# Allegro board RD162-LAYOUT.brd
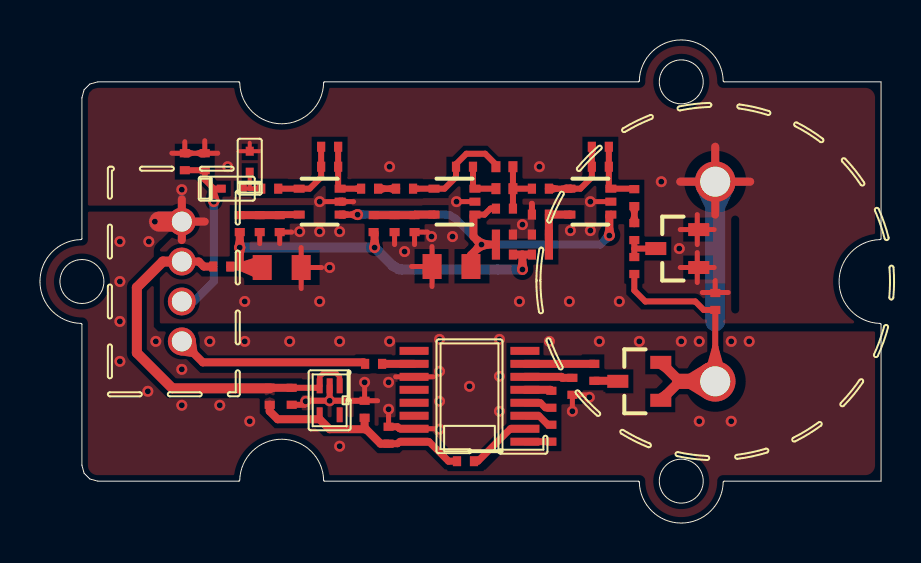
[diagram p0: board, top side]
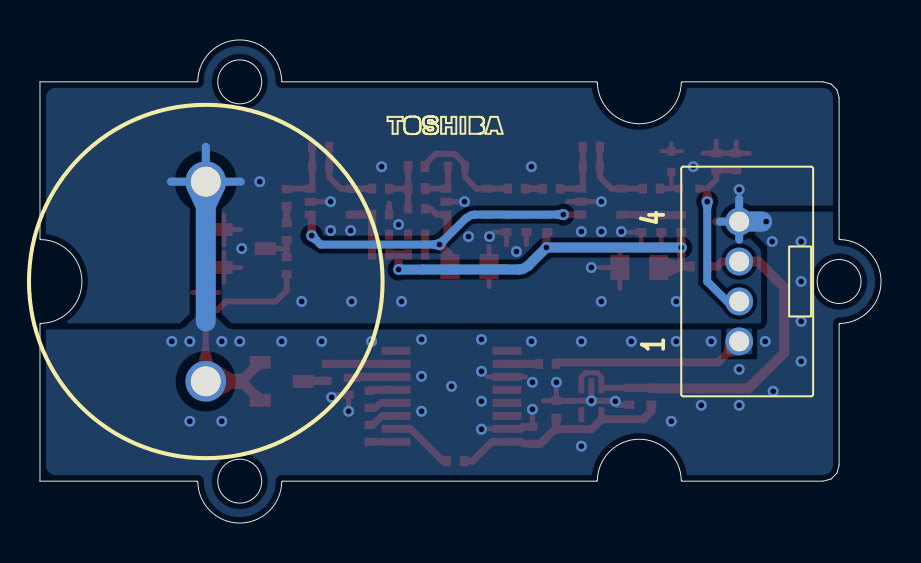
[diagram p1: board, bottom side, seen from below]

Outline 42.1 x 24.2 mm; copper layers: TOP, BOTTOM. Coordinates in mm from the lower left corner of the outline.
Outline path: circle c2.1,12.1 r1.1 ; circle c32.1,22.1 r1.1 ; circle c32.1,2.1 r1.1 ; 2.05,14.2 2.09,14.21 2.1,14.25 2.1,21.3 2.21,21.7 2.5,21.99 2.9,22.1 9.95,22.1 9.99,22.09 10,22.05 arc(12.1,20) 14.2,22.05 14.21,22.09 14.25,22.1 29.95,22.1 29.99,22.11 30,22.15 arc(32.1,24.2) 34.2,22.15 34.21,22.11 34.25,22.1 42.1,22.1 42.1,14.25 42.09,14.21 42.05,14.2 arc(40,12.1) 42.05,10 42.09,9.99 42.1,9.95 42.1,2.1 34.25,2.1 34.21,2.09 34.2,2.05 arc(32.1,0) 30,2.05 29.99,2.09 29.95,2.1 14.25,2.1 14.21,2.11 14.2,2.15 arc(12.1,4.2) 10,2.15 9.99,2.11 9.95,2.1 2.9,2.1 2.5,2.21 2.21,2.5 2.1,2.9 2.1,9.95 2.09,9.99 2.05,10 arc(0,12.1) 2.05,14.2

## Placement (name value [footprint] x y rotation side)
C1  -  [KC00050ACP]  25.6 4.5 270 top
C2  -  [KC00050ACP]  21.3 3.1 180 top
C3  -  [KC00050ACP]  17.45 4.4 270 top
C4  -  [KC00050ACP]  25.6 6.2 270 top
C5  -  [KC00050ACP]  26.65 6.85 90 top
C6  -  [KC00050ACS]  16.25 5.7 270 top
C7  -  [KC00050ACP]  27.75 7.55 90 top
C8  -  [KC00050ACP]  12.6 6.35 90 top
C9  -  [DC834K0ACP]  28.05 18.85 180 top
C10  -  [KC00050ACP]  29.75 14.6 90 top
C11  -  [DC834K0ACP]  14.5 18.85 180 top
C12  -  [KC01540AKP01]  23.25 17.85 180 top
C13  -  [KC00060ATP]  12.1 12.8 180 top
C14  -  [KC01540AKP01]  23.25 16.75 180 top
C15  -  [KC00050ACP]  18.25 16.75 180 top
C16  -  [KC00050ACP]  25.05 14.45 0 top
C17  -  [KC00050ACP]  25.05 15.45 0 top
C18  -  [KC00050ACP]  17.75 15 90 top
C19  -  [KC00050ACP]  18.75 15 90 top
C20  -  [KC00050ACP]  11.5 16.75 180 top
C21  -  [KC00060ATP]  20.6 12.85 0 top
C22  -  [DC834K0ACP]  8.25 18.1 270 top
C23  -  [KC00050ACP]  12 15 90 top
C24  -  [KC00050ACP]  11 15 90 top
CN1  -  [CUP10060ATP]  7.1 9.1 90 bottom
D1  -  [MMK01261AKP]  30 7.1 90 top
D2  -  [MMK01261AKP]  31.9 13.75 90 top
D3  -  [MM00820ACP]  9.6 16.75 180 top
D4  -  [MM00820ACP]  10.5 18.1 270 top
JP1  -  [KC00050ACP]  11.5 6.35 90 top
NOREF  -  []  25.55 18.65 0 top
R1  -  [DR824K0ACP]  16.7 7.97 180 top
R2  -  [KC00050ACP]  9.1 12.85 180 top
R3  -  [DR824K0ACP]  29.75 12.9 90 top
R4  -  [KC00050ACP]  29.75 16.3 90 top
R5  -  [KC00050ACP]  28.05 17.85 180 top
R6  -  [DR824K0ACP]  21.25 17.85 0 top
R7  -  [KC00050ACP]  25.05 16.75 180 top
R8  -  [DR824K0ACP]  16.5 16.75 180 top
R9  -  [DR824K0ACP]  14.5 17.85 180 top
R10  -  [KC00050ACP]  25.05 13.45 180 top
R11  -  [DR824K0ACP]  33.8 11.1 90 top
R12  -  [KC00050ACP]  16.7 15 270 top
R13  -  [DR824K0ACP]  23.25 15.75 180 top
R14  -  [DR824K0ACP]  23.25 14.45 0 top
R15  -  [DR824K0ACP]  23.25 13.45 0 top
R16  -  [KC00050ACP]  10 15 270 top
R17  -  [KC00050ACP]  7.25 18.1 90 top
U1  -  [DIA817C]  14.5 6.15 180 top
U2  -  [DIA863C]  21.5 6.35 90 top
U3  -  [MM00380ACP]  27.55 16.1 90 top
U4  -  [MM00380ACP]  20.75 16.1 90 top
U5  -  [RDP10030ATP]  33.8 7.1 90 bottom
U6  -  [MM00380ACP]  14 16.1 90 top

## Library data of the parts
C1-C5 C7 C8 C17 C19 C24 = GDM030002515: alternate symbols: (T:KC00050ACP;B:KC00050BCP)
C6 = GDM030000207: alternate symbols: (T:KC00050ACS;B:KC00050BCS)
C9 = G36030133319: alternate symbols: (T:DC834K0ACP;B:DC834K0BCP)
C10 C15 = GDM030002207: alternate symbols: (T:KC00050ACP;B:KC00050BCP)
C11 = G36030133067: alternate symbols: (T:DC834K0ACP;B:DC834K0BCP)
C12 C14 = GAS030000198: alternate symbols: (T:KC01540AKP01;B:KC01540BKP01)
C13 = GDM030001363: alternate symbols: (T:KC00060ATP;B:KC00060BTP)
C16 C18 C20 C23 = GDM030002441: alternate symbols: (T:KC00050ACP;B:KC00050BCP)
C21 = GDM030002136: alternate symbols: (T:KC00060ATP;B:KC00060BTP)
C22 = G36030133234: alternate symbols: (T:DC834K0ACP;B:DC834K0BCP)
CN1 = K22S001P: alternate symbols: (T:CUP10060ATP;B:CUP10060BTP)
D1 D2 = K4200526: alternate symbols: (T:MMK01261AKP;B:MMK01261BKP)
D3 D4 = GDM420000214: alternate symbols: (T:MM00820ACP;B:MM00820BCP)
JP1 R2 R10 R12 R16 = GDM010002886: alternate symbols: (T:KC00050ACP;B:KC00050BCP)
R1 R3 R14 R15 = GDM010001350: alternate symbols: (T:DR824K0ACP;B:DR824K0BCP)
R4 R17 = GDM010004244: alternate symbols: (T:KC00050ACP;B:KC00050BCP)
R5 = GDM010001678: alternate symbols: (T:KC00050ACP;B:KC00050BCP)
R6 = G36010118497: alternate symbols: (T:DR824K0ACP;B:DR824K0BCP)
R7 = K0100567: alternate symbols: (T:KC00050ACP;B:KC00050BCP)
R8 = G36010118343: alternate symbols: (T:DR824K0ACP;B:DR824K0BCP)
R9 = G36010118060: alternate symbols: (T:DR824K0ACP;B:DR824K0BCP)
R11 = G36010118633: alternate symbols: (T:DR824K0ACP;B:DR824K0BCP)
R13 = G36010118619: alternate symbols: (T:DR824K0ACP;B:DR824K0BCP)
U1 = GDM470001887: alternate symbols: (T:DIA817C;B:DIA917C)
U2 = K47S002D: alternate symbols: (T:DIA863C;B:DIA963C)
U3 U4 U6 = K47S002A: alternate symbols: (T:MM00380ACP;B:MM00380BCP)
U5 = K30S0001: alternate symbols: (T:RDP10030ATP;B:RDP10030BTP)

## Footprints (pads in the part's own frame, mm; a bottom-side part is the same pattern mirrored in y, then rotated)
CUP10060ATP
  round 1.397 hole 1: 1(0,0) 2(2,0) 3(4,0) 4(6,0)
DC834K0ACP
  rect 0.41x0.5 smd: 1(-0.425,0) 2(0.425,0)
DIA817C
  rect 0.3x0.75 smd: 1(-0.5,-0.725) 2(0,-0.725) 3(0.5,-0.725) 4(0.5,0.725) 5(-0.5,0.725)
DIA863C
  rect 0.4x1.45 smd: 1(-2.275,-2.775) 2(-1.625,-2.775) 3(-0.975,-2.775) 4(-0.325,-2.775) 5(0.325,-2.775) 6(0.975,-2.775) 7(1.625,-2.775) 8(2.275,-2.775) 9(2.275,2.775) 10(1.625,2.775) 11(0.975,2.775) 12(0.325,2.775) 13(-0.325,2.775) 14(-0.975,2.775) 15(-1.625,2.775) 16(-2.275,2.775)
DR824K0ACP
  rect 0.41x0.5 smd: 1(-0.425,0) 2(0.425,0)
KC00050ACP
  rect 0.41x0.5 smd: 1(-0.425,0) 2(0.425,0)
KC00050ACS
  rect 0.41x0.5 smd: 1(-0.425,0) 2(0.425,0)
KC00060ATP
  rect 0.95x1.25 smd: 1(-0.975,0) 2(0.975,0)
KC01540AKP01
  rect 0.45x0.55 smd: 1(-0.425,0) 2(0.425,0)
MM00380ACP
  rect 0.4x0.55 smd: 1(-0.65,-1.025) 2(0,-1.025) 3(0.65,-1.025) 4(0.65,1.025) 5(-0.65,1.025)
MM00820ACP
  rect 0.45x0.4 smd: A(-0.525,0) C(0.525,0)
MMK01261AKP
  rect 0.65x1.05 smd: A(-0.95,-1.075) AC(0,1.075) C(0.95,-1.075)
RDP10030ATP
  round 2.032 hole 1.5: 1(0,0) 2(10,0)

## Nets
GND: C3.1(TP-1) C5.1(TP-1) C6.1(TP-1) C8.1(TP-1) C13.1(TP-1) C16.1(TP-1) C17.1(TP-1) C18.1(TP-1) C19.1(TP-1) C21.1(TP-1) C22.1(TP-1) C23.1(TP-1) C24.1(TP-1) CN1.4 D2.A D2.C D4.A R11.2(TP-1) R14.2(TP-1) R17.2(TP-1) U1.2 U2.11 U2.15 U3.2 U4.2 U5.2(TP-1) U6.2
VCC: C13.2(TP-1) R2.1(TP-1) R10.2(TP-1) R12.2(TP-1) R15.2(TP-1) R16.2(TP-1)
SIG76: D1.A D1.C R3.1(TP-1) R11.1(TP-1) U5.1(TP-1)
SIG78: C10.2(TP-1) R4.1(TP-1)
SIG83: C16.2(TP-1) C17.2(TP-1) R10.1(TP-1) U3.5
SIG86: C12.1(TP-1) C14.1(TP-1) R7.2(TP-1) R13.1(TP-1)
SIG109: C1.2(TP-1) U2.1
SIG110: C1.1(TP-1) U2.3
SIG111: C4.2(TP-1) U2.4
SIG112: C4.1(TP-1) U2.5
SIG113: C2.1(TP-1) U2.2
SIG127: C7.2(TP-1) U2.7
SIG130: R1.1(TP-1) U2.10
SIG131: CN1.1 R1.2(TP-1)
SIG132: C7.1(TP-1) D1.AC
SIG136: C9.1(TP-1) R4.2(TP-1) R5.1(TP-1) U3.3
SIG137: C9.2(TP-1) R5.2(TP-1) R7.1(TP-1) U3.4
SIG138: C18.2(TP-1) C19.2(TP-1) R12.1(TP-1) U4.5
SIG141: C12.2(TP-1) C15.1(TP-1) R6.1(TP-1) U4.4
SIG143: C11.1(TP-1) R8.2(TP-1) R9.1(TP-1) U6.3
SIG145: C23.2(TP-1) C24.2(TP-1) R16.1(TP-1) U6.5
SIG146: C11.2(TP-1) C20.1(TP-1) R9.2(TP-1) U6.4
SIG147: C20.2(TP-1) D3.A D4.C
SIG152: C2.2(TP-1) C3.2(TP-1) C6.2(TP-1) JP1.1(TP-1) U1.4 U2.16
SIG154: C8.2(TP-1) CN1.3 JP1.2(TP-1) R2.2(TP-1) U1.1 U1.3
SIG155: C22.2(TP-1) CN1.2 D3.C R17.1(TP-1)
SIG156: C10.1(TP-1) D2.AC R3.2(TP-1)
SIG157: C14.2(TP-1) R6.2(TP-1) U4.3
SIG159: C15.2(TP-1) R8.1(TP-1)
SIG162: C5.2(TP-1) U2.6
VCC/2: C21.2(TP-1) R13.2(TP-1) R14.1(TP-1) R15.1(TP-1) U3.1 U4.1 U6.1

Pads without a net: U1 5; U2 8 9 12 13 14

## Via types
v1: diameter 0.55, hole 0.3, TOP to BOTTOM, 73 vias

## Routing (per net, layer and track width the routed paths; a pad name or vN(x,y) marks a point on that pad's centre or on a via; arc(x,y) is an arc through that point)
GND: length 66.9
  TOP w0.2: D4.A 11,18.62 ; D4.A 9.95,18.62 ; D4.A 10.5,19.05
  TOP w0.25: 12.6,14.57 C23.1 12,14 ; 16.9,6.12 C6.1 v1(16.25,7.05) ; 32.9,13.55 32.9,12.05 ; C13.1 14.1,12.8 ; C13.1 13.07,11.75 ; C13.1 13.07,13.8 ; 21.74,16.1 20.95,16.1 ; 17.8,7.32 U2.11 19.7,7.32 ; 26.65,5.8 C5.1 27.3,6.42 ; 33.75,14.7 D2.C 32.9,14.7 ; C21.1 19.62,13.85 ; C21.1 19.62,11.85 ; C21.1 18.6,12.85 ; 33.15,11.55 34.45,11.55 ; 32.05,12.8 D2.A 33.75,12.8 ; 18.75,13.95 C19.1 19.4,14.57 ; 33.8,12.15 R11.2 ; 15.12,16.1 15.7,16.1 ; 32.9,14.7 32.05,14.7 ; 32.9,14.7 32.9,13.95 ; 32.9,14.7 32.9,15.45 ; 6.6,18.52 7.25,18.52 7.25,19.1 ; 14.99,16.1 v1(14,16.1) ; v1(17.45,5.7) C3.1 ; C24.1 11,14 ; 7.39,18.52 8.11,18.52 ; 8.9,18.52 8.25,18.52 8.25,19.15 ; C18.1 17.75,13.95 ; 28.54,16.1 27.75,16.1 ; U2.15 19.75,4.72
  TOP w0.3: v1(14.5,6.12) 13.45,6.12 13.25,5.92 C8.1 ; v1(14.5,6.12) C6.1 ; v1(14.5,6.12) U1.2 ; C17.1 24.62,16
  TOP w0.35: C3.1 17.9,4.82 18,4.72 U2.15
  TOP w0.4: CN1.4 8.25,15.1 ; CN1.4 7.1,16.2 ; CN1.4 7.1,14.17 ; U5.2 33.8,15.45 ; U5.2 33.8,18.85 ; U5.2 35.55,17.1 ; U5.2 32.05,17.1 ; U6.2 15.12,16.1
  TOP w0.41: 8.11,18.52 8.25,18.52 ; 7.25,18.52 7.39,18.52
  TOP w1: CN1.4 5.97,15.1
  BOTTOM w0.4: CN1.4 8.06,15.1 ; CN1.4 7.1,16.25 ; CN1.4 7.1,14.2 ; U5.2 32.05,17.1 ; U5.2 35.55,17.1 ; U5.2 33.8,18.85
  BOTTOM w1: CN1.4 5.95,15.1 ; U5.2 33.8,10.1
  vias: v1(4,14.1) v1(4,12.1) v1(4,10.1) v1(4,8.1) v1(5.4,6.6) v1(5.45,14.1) v1(5.75,15.1) v1(5.8,9.1) v1(7.1,16.7) v1(7.1,7.7) v1(7.1,5.9) v1(8.5,9.1) v1(9,5.9) v1(9.4,17.85) v1(10.25,11.1) v1(10.25,9.1) v1(10.5,5.1) v1(12.5,9.1) v1(13,14.6) v1(13.3,6.1) v1(14,14.6) v1(14,11.1) v1(14.5,12.8) v1(15,14.6) v1(15,9.1) v1(15,3.85) v1(17.45,7.05) v1(17.5,17.85) v1(17.5,9.1) v1(18.25,13.6) v1(19.6,14.35) v1(20,9.2) v1(20,7.6) v1(20,6.1) v1(20,4.7) v1(20.65,14.35) v1(20.85,16.1) v1(21.5,6.85) v1(23,9.2) v1(23,7.35) v1(23,5.6) v1(24,11.1) v1(24.15,14.95) v1(25,17.85) v1(25.5,9.1) v1(26.5,11.1) v1(26.55,14.65) v1(26.65,5.6) v1(27.5,6.3) v1(27.55,16.1) v1(27.55,14.65) v1(28,9.1) v1(29,11.1) v1(30,9.1) v1(31.1,17.1) v1(32,13.75) v1(32.1,9.1) v1(33,9.1) v1(33,5.1) v1(34.6,9.1) v1(34.6,5.1) v1(35.5,9.1)
VCC: length 22.9
  TOP w0.4: R10.2 24.15,13.45 ; 24.15,13.45 v1(24.15,12.7) ; 24.15,13.45 R15.2 ; R12.2 16.75,14.52 v1(16.75,13.8) ; C13.2 10.8,12.5 10,12.85 ; 10,12.85 v1(10,13.8) R16.2 ; 10,12.85 10.8,13.1 11.07,12.85 10,12.85 ; 10,12.85 R2.1
  BOTTOM w0.5: 22.92,12.7 v1(24.15,12.7)
  BOTTOM w0.508: 22.92,12.7 18.11,12.7 17.95,12.72 17.66,12.89 v1(16.75,13.8) v1(10,13.8)
SIG76: length 17.5
  TOP w0.3: 33.8,8.82 34.25,7.22 U5.1 ; 33.8,8.82 U5.1 ; 33.8,8.82 33.8,10.67 33.22,10.67 32.8,11.1 30.3,11.1 29.75,11.65 R3.1 ; 33.8,8.82 33.35,7.22 U5.1
  TOP w0.5: D1.C 32,7.12 ; 32.02,7.1 D1.A
  TOP w0.762: U5.1 32.02,7.1
SIG78: length 0.8
  TOP w0.3: 29.75,15.18 29.75,15.72
  TOP w0.41: C10.2 29.75,15.18 ; 29.75,15.72 R4.1
SIG83: length 3.1
  TOP w0.4: R10.1 C16.2 C17.2 26.56,15.45
SIG86: length 3
  TOP w0.3: C14.1 C12.1 ; C14.1 R13.1 ; C14.1 24.57,16.75
SIG109: length 1.3
  TOP w0.35: 24.27,4.07 C1.2
SIG110: length 1.5
  TOP w0.35: U2.3 24.97,5.37 25.42,4.92 C1.1
SIG111: length 1.4
  TOP w0.35: U2.4 25.05,6.02 25.3,5.77 C4.2
SIG112: length 1.3
  TOP w0.4: U2.5 25.55,6.67 C4.1
SIG113: length 3.2
  TOP w0.35: C2.1 21.92,3.1 23.55,4.72 U2.2
SIG127: length 3.5
  TOP w0.4: U2.7 C7.2
SIG130: length 1.6
  TOP w0.4: U2.10 R1.1
SIG131: length 9.6
  TOP w0.4: CN1.1 8.15,8.05 16.2,8.05 R1.2
SIG132: length 1.2
  TOP w0.4: C7.1 28.9,7.12 D1.AC
SIG136: length 3.3
  TOP w0.3: R4.2 29.72,16.75 U3.3 28.54,16.75 28.47,16.81 R5.1 C9.1
SIG137: length 3.9
  TOP w0.3: C9.2 R5.2 27.62,17.32 27.05,16.75 26.55,16.75 ; 25.63,16.75 26.37,16.75
  TOP w0.4: 26.37,16.75 26.55,16.75
  TOP w0.41: R7.1 25.63,16.75
SIG138: length 3.1
  TOP w0.4: 19.76,15.45 U4.5 18.77,15.45 C19.2 C18.2 R12.1
SIG141: length 5.6
  TOP w0.3: C15.1 U4.4 20.25,16.75 20.82,17.32 R6.1 20.82,17.98 21.35,18.5 22.28,18.5 22.82,17.96 C12.2
SIG143: length 3.2
  TOP w0.3: R8.2 U6.3 14.99,16.75 14.92,16.81 R9.1 C11.1
SIG145: length 3
  TOP w0.35: 13.01,15.45 U6.5 12.02,15.45 C23.2
  TOP w0.4: C23.2 C24.2 R16.1
SIG146: length 3.9
  TOP w0.3: C20.1 U6.4 13.5,16.75 14.07,17.32 R9.2 C11.2
SIG147: length 2.5
  TOP w0.2: D3.A 10.5,16.75 D4.C
  TOP w0.25: 10.75,16.75 11,16.65 C20.2 ; 10.75,16.75 10.5,16.75 ; 10.75,16.75 C20.2 ; 10.75,16.75 11,16.82 C20.2
SIG152: length 11.4
  TOP w0.35: C3.2 17.9,3.97 18,4.07 19.47,4.07 20.45,3.1 C2.2
  TOP w0.4: 16.25,4.7 14.5,4.7 14,5.2 11.9,5.2 11.5,5.6 JP1.1 ; 16.25,4.7 C6.2 ; 16.25,4.7 16.32,4.7 17.05,3.97 C3.2
SIG154: length 19.7
  TOP w0.25: U1.1 15,7.32 14.8,7.52 14.2,7.52 14,7.32 U1.3
  TOP w0.3: 12.6,6.77 13.9,6.77 U1.3
  TOP w0.4: 11.5,6.77 12.6,6.77 ; 8.67,12.85 8.2,12.85 7.95,13.1 CN1.3
  TOP w0.5: 11.5,6.75 6.62,6.75 4.85,8.52 4.85,11.8 6.15,13.1 CN1.3
SIG155: length 10.4
  TOP w0.3: v1(8.7,16.1) 8.55,16.15 8.7,16.6 ; v1(8.7,16.1) 8.7,16.6 ; v1(8.7,16.1) 8.85,16.15 8.7,16.6 ; 8.7,16.6 8.7,16.75 ; D3.C 8.7,16.75 ; 8.7,16.75 8.25,17.2 C22.2 R17.1
  BOTTOM w0.4: v1(8.7,16.1) 8.7,12.1 7.7,11.1 CN1.2
SIG156: length 1.9
  TOP w0.3: 29.75,13.32 29.75,13.75 ; 29.75,13.75 29.75,14.17 ; 29.75,13.75 D2.AC
SIG157: length 2.1
  TOP w0.3: 21.74,16.75 U4.3 C14.2 ; R6.2 21.67,16.81
SIG159: length 0.9
  TOP w0.3: 17.08,16.75 17.67,16.75
  TOP w0.41: R8.1 17.08,16.75 ; 17.67,16.75 C15.2
SIG162: length 2.4
  TOP w0.4: U2.6 26.1,7.32 26.15,7.27 26.65,7.27
VCC/2: length 21.2
  TOP w0.3: 21.74,15.45 U4.1 22.25,15.45 22.55,15.75 R13.2 ; v1(15.9,15.45) 15.18,15.45
  TOP w0.4: v1(22.1,13.95) 21.57,13.42 C21.2 ; v1(22.1,13.95) 21.7,14.35 21.7,15.4 ; v1(22.1,13.95) 22.82,13.95 ; R14.1 22.82,13.95 ; 22.82,13.95 R15.1 ; 15.18,15.45 U6.1 ; v1(28.5,14.4) 28.5,15.37 U3.1
  BOTTOM w0.4: v1(15.9,15.45) 20.34,15.45 20.5,15.43 20.79,15.26 v1(22.1,13.95) 28.05,13.95 v1(28.5,14.4)

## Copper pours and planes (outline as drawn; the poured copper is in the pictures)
GND on TOP: 13.17,7.2 13.13,7.21 13.1,7.25 6.83,7.25 6.8,7.26 6.78,7.27 5.37,8.68 5.36,8.7 5.35,8.73 5.35,11.59 5.36,11.62 5.37,11.65 5.57,11.85 5.65,11.86 5.7,11.79 5.7,9.82 5.92,9.6 6.22,9.6 6.29,9.56 6.29,9.49 6.38,8.56 7.25,8.21 7.32,8.21 7.34,8.2 7.36,8.19 8.03,7.52 13.65,7.52 13.7,7.5 13.72,7.45 13.72,7.41 13.72,7.38 13.7,7.35 13.67,7.32 13.65,7.31 13.62,7.3 13.6,7.3 13.6,7.27 13.58,7.22 13.52,7.2
GND on TOP: outline of 214 points within 0.3,0.3 41.8,15.6 ; 2 cut-outs
GND on TOP: outline of 332 points within 2.4,10 41.8,23.9 ; 9 cut-outs
GND on TOP: outline of 95 points within 13.1,4.87 17.9,7.5
GND on BOTTOM: 34.6,15.25 34.59,15.29 34.59,15.72 34.6,15.76 34.63,15.79 33.81,18.65 32.97,15.79 32.99,15.77 33,15.73 33,10.53 32.99,10.5 32.98,10.48 32.52,10.02 32.5,10.01 32.47,10 6.07,10 6.02,10.02 6,10.07 6,13.49 6.04,13.68 6.15,13.85 6.55,14.25 6.59,14.27 6.63,14.26 6.79,14.19 6.95,14.15 7.18,14.15 7.2,14.15 7.21,14.14 7.25,14.15 8,15.44 6.58,15.91 6.57,15.9 6.54,15.9 2.5,15.9 2.43,15.91 2.4,15.97 2.4,21.3 2.47,21.55 2.65,21.73 2.9,21.8 9.65,21.8 9.7,21.78 9.73,21.74 12.1,19.7 14.47,21.74 14.5,21.78 14.55,21.8 30,21.8 30.21,21.89 30.3,22.1 32.1,23.9 33.9,22.1 33.99,21.89 34.2,21.8 41.3,21.8 41.65,21.65 41.8,21.3 41.8,14.55 41.78,14.5 41.74,14.47 39.76,12.65 40.72,10.14 40.75,10.05 40.68,10 35.13,10 35.1,10.01 35.08,10.02 34.62,10.48 34.61,10.5 34.6,10.53 ; 5 cut-outs
GND on BOTTOM: 14.55,2.4 14.5,2.42 14.47,2.46 12.1,4.5 9.73,2.46 9.7,2.42 9.65,2.4 2.9,2.4 2.65,2.47 2.47,2.65 2.4,2.9 2.4,10 2.31,10.21 2.1,10.3 0.3,12.1 2.1,13.9 2.31,13.99 2.4,14.2 2.4,15.53 2.4,15.55 2.44,15.6 2.5,15.6 6.15,15.6 6.22,15.57 6.23,15.5 6.22,15.49 6.14,15.02 6.3,14.57 6.3,14.55 6.31,14.53 6.31,14.49 6.3,14.46 6.29,14.44 5.7,13.85 5.7,10.12 5.82,9.82 6.18,9.68 6.2,9.62 6.2,8.2 8,8.2 8,9.62 8.02,9.68 8.07,9.7 32.44,9.7 32.69,9.77 32.8,9.85 33.53,10.58 33.55,10.59 33.58,10.6 34.02,10.6 34.05,10.59 34.07,10.58 34.8,9.85 35.03,9.72 35.16,9.7 41.7,9.7 41.76,9.7 41.8,9.65 41.8,9.63 41.8,2.9 41.65,2.55 41.3,2.4 34.2,2.4 33.99,2.31 33.9,2.1 32.1,0.3 30.3,2.1 30.21,2.31 30,2.4 ; 3 cut-outs
SIG131 on BOTTOM: 6.52,8.45 6.47,8.47 6.45,8.52 6.45,9.67 6.47,9.73 6.52,9.75 7.67,9.75 7.73,9.73 7.75,9.67 7.75,8.52 7.73,8.47 7.67,8.45
SIG152 on TOP: 11.32,5.7 11.27,5.72 11.25,5.77 11.25,6.15 11.26,6.19 11.29,6.22 11.47,6.31 11.5,6.32 11.54,6.31 11.71,6.22 11.74,6.19 11.75,6.15 11.75,5.77 11.73,5.72 11.67,5.7

Small or netless copper shapes (teardrops, artwork), in the pictures only: 29 on TOP, 6 on BOTTOM

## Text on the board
Ref Des/Silkscreen Bottom: 4 | 1
SYMBOL-1-BOTTOM: 4 | 1
SYMBOL-2-BOTTOM: GROVE-D | U5 | CN1 | 4 | 1
User.6: D3 | Gnd | Puls | Vcc | Out | C20 | R2 | JP1 | C13 | C8 | U6 | U1 | R8 | C11 | R9 | C6 | C3 | R1 | C15 | U4 | C2 | C21 | R6 | U2 | U3 | C5 | C4 | C1 | C7 | C10 | R3 | C9 | R5 | D1 | R4 | D2 | R11 | C12 | C14 | R13 | R14 | R15 | R7 | C17 | C16 | R10 | R16 | C24 | C23 | R17 | C22 | D4 | R12 | C18 | C19
